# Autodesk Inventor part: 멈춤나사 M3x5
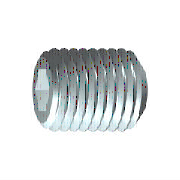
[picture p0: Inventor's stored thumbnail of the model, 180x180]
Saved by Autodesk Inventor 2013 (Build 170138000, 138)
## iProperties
Created: 2012-02
Part Number: 멈춤나사 M3x5
Material: 강철, 연강
Description: 6각 소켓 머리 없는 멈춤 나사
Document SubType Name: Modeling
Standard: KS B 1028
Designer: mduedu
Standards Organization: KS
Language: ko-KR
Size Designation: 납작점M3x5
Categories: <MemberInstance><Categories><Category DisplayName="조임쇠" InternalName="e4da775c-781d-43d5-af7c-5136215cf5a6" Mnemonic="FSTN"><Category DisplayName="볼트" InternalN
Density: 1 g/cm^3
IsCustomPart: 1
Author: mduedu
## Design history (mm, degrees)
sketch "스케치1"
  geometry: L1 (0, 0)-(2.5, 0); L2 (5, 0.866)-(5, 1.5); L3 (5, 1.5)-(0, 1.5); L4 (5, 0.866)-(3, 0.866); L5 (3, 0.866)-(2.5, 0); L6 (0, -0.3)-(0, 1.8) reference; L7 (0, 1.5)-(0, 0)
  constraints: 13 end point, 3 parallel, 1 collinear, 1 perpendicular, 1 point on line
  dimensions: "d0" = 2 distance of L2.start L4.end (= INTI); "d1" = 60 deg angle of L5 L1; "d2" = 3 diameter of L3 L1 (= NND); "d3" = 1.73205 diameter of L4 L1 (= 1.1547 x SW); "d5" = 5 distance from line of L2 L3.end (= NLG)
revolve "본체" sketch "스케치1" stored, may be unused: angle "d6" = 90 deg
sketch "스케치2"
  geometry: L1 (-0.433, 0.75)-(0.433, 0.75); L2 (0.433, 0.75)-(0.866, 0); L3 (0.866, 0)-(0.433, -0.75); L4 (0.433, -0.75)-(-0.433, -0.75); L5 (-0.433, -0.75)-(-0.866, 0); L6 (-0.866, 0)-(-0.433, 0.75); A1 r 0.866 centre (0, 0) between (-0.433, 0.75) and (0.433, 0.75) reference; 2 further points
  constraints: 12 end point, 2 point on circle, 1 coincident, 1 horizontal, 11 other
extrude "슬롯" join sketch "스케치2" taper "d9" = 0 deg; stored distance "d21" = 10
workaxis "Work Axis1"
workplane "Work Plane1"
body "Solid1"
chamfer "모따기1" distance "d7" = 0.30673 (= -0.5 x GD1 + 0.5 x NND); stored, may be unused: angle "d8" = 45 deg (= FAWI), second distance "d29" = 0.30673 (= -0.5 x GD1 + 0.5 x NND)
feature "스레드" dims "d11" = 5 (= NLG), "d12" = 0
chamfer "모따기2" distance "d13" = 0.30673 (= -0.5 x GD1 + 0.5 x NND); stored, may be unused: angle "d14" = 45 deg (= FAWI), second distance "d30" = 0.30673 (= -0.5 x GD1 + 0.5 x NND)
other parameters: "NND" = 3 [user parameter; used in 5 equation terms], "NLG" = 5 [user parameter; used in 2 equation terms], "INTI" = 2 [user parameter; used in 1 equation term], "FAWI" = 45 deg [user parameter; used in 2 equation terms], "SW" = 1.5 [user parameter; used in 2 equation terms], "GD1" = 2.38655 (= THREADDIA - 1.2269 x PTC) [user parameter; used in 4 equation terms], "d4" = 0, "FAWI1" = 45 deg [user parameter], "d15" = 0, "d31" = 0, "GUL" = 0.30673 (= 0.61345 x PTC) [user parameter], "SPD" = 2 [user parameter], "TOA" = 30 deg [user parameter], "THREADDIA" = 3 [user parameter; used in 1 equation term], "PTC" = 0.5 [user parameter; used in 4 equation terms], "GAL" = 0.30673 (= 0.61345 x PTC) [user parameter], "E0" = 1.7325 (= 1.155 x SW) [user parameter]
